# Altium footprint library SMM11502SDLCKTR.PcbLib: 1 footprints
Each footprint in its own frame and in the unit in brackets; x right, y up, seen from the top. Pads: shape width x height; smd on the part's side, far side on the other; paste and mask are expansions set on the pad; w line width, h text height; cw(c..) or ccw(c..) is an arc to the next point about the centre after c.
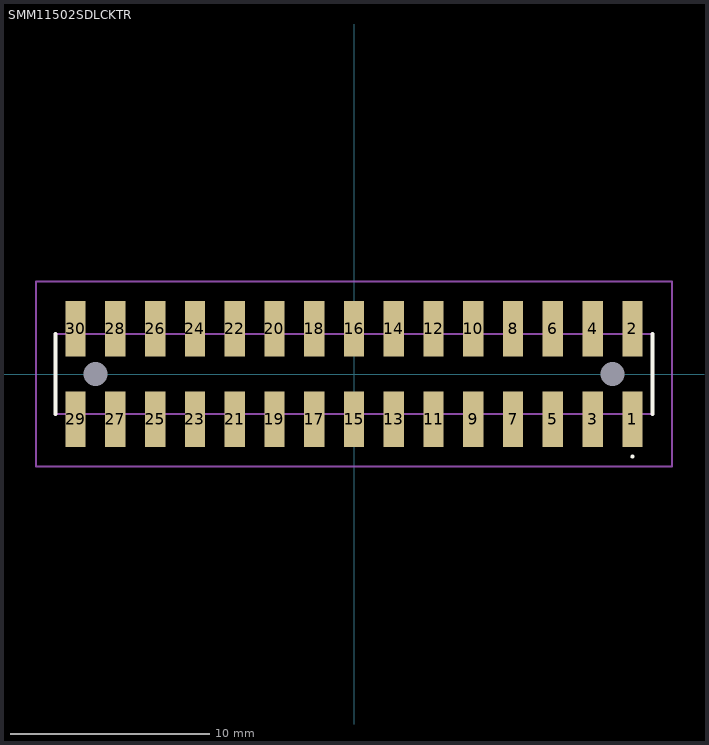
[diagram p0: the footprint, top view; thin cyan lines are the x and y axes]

## SMM11502SDLCKTR [mm]
pads (32):
  rect 1.02x2.77 smd: 1(14,-2.275) 2(14,2.275) 3(12,-2.275) 4(12,2.275) 5(10,-2.275) 6(10,2.275) 7(8,-2.275) 8(8,2.275) 9(6,-2.275) 10(6,2.275) 11(4,-2.275) 12(4,2.275) 13(2,-2.275) 14(2,2.275) 15(0,-2.275) 16(0,2.275) 17(-2,-2.275) 18(-2,2.275) 19(-4,-2.275) 20(-4,2.275) 21(-6,-2.275) 22(-6,2.275) 23(-8,-2.275) 24(-8,2.275) 25(-10,-2.275) 26(-10,2.275) 27(-12,-2.275) 28(-12,2.275) 29(-14,-2.275) 30(-14,2.275)
  round 0.595 hole 1.19 unplated: MH1(13,0) MH2(-13,0)
Top Overlay:
  lines w0.1: 14,-4.2 cw(c14,-4.15) 14,-4.1 ; 14,-4.2 14,-4.2 ; 14,-4.2 ccw(c14,-4.15) 14,-4.1 ; 14,-4.1 14,-4.1
  lines w0.2: -15,-2.001 -15,2.001 ; 15,-2.001 15,2.001
Mechanical 15:
  lines w0.1: -15,-2.001 15,-2.001 15,2.001 -15,2.001 -15,-2.001
Mechanical 20:
  lines w0.1: -16,-4.66 16,-4.66 16,4.66 -16,4.66 -16,-4.66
